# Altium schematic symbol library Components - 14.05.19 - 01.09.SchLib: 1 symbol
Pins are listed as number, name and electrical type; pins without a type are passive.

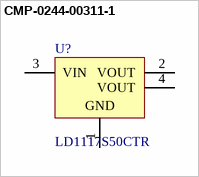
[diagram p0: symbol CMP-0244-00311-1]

## CMP-0244-00311-1
designator U?, comment LD1117S50CTR
Fixed Low Drop Positive Voltage Regulator, 5V, 4-Pin SOT-223, Tape and Reel
footprint SOT-223_L (SOT223, 4-Leads, Body 6.5x3.5mm, Pitch 2.3mm, Lead Span 7mm, IPC High Density)
footprint SOT-223_N (SOT223, 4-Leads, Body 6.5x3.5mm, Pitch 2.3mm, Lead Span 7mm, IPC Medium Density)
footprint SOT-223_M (SOT223, 4-Leads, Body 6.5x3.5mm, Pitch 2.3mm, Lead Span 7mm, IPC Low Density)
pins: 1 GND (power), 2 VOUT (power), 3 VIN (power), 4 VOUT (power)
